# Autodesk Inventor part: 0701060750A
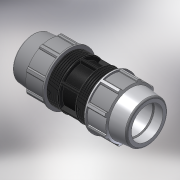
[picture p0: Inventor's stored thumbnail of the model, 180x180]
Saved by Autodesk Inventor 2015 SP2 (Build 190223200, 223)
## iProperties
Created: 2017-02
Part Number: 0701060750A
Material: Generic
Description: PLASSON COUPLER 75-75
Document SubType Name: Modeling
Designer: KIM
Mass: 3885.53 g
Surface Area: 4713.66 cm^2
Volume: 3885.53 cm^3
Density: 1 g/cm^3
Appearance: Default
Author: KIM
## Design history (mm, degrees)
derived "87010.ipt"
feature "Solid1::87010.ipt"
tag "TaggingFeature1"
body "Solid1"
other parameters: "d1" = 278, "d2" = 75, "d4" = 23.16667, "d5" = 39.71429, "d7" = 134, "d8" = 100.5, "d9" = 39.71429, "d11" = 3.97143, "d12" = 107.2, "d13" = 120 deg, "d14" = 105, "d15" = 6 deg, "d16" = 120.6, "d18" = 3.75, "d19" = 35 deg, "d20" = 17.5 deg, "d21" = 124.62, "d23" = 0, "d25" = 360 deg, "d27" = 2.68, "d33" = 1.5, "d34" = 6.7, "d36" = 0, "d37" = 1.5, "d38" = 1.5, "d40" = 360 deg, "d42" = 50.04, "d46" = 2.25, "d50" = 3.475, "d51" = 0, "d53" = 2.54171, "d54" = 2.54171, "d57" = 5.08343, "d62" = 118.188, "d64" = 67.5, "d65" = 138, "d_" = 75, "E_" = 134, "H_" = 278, "l_" = 138, "d52" = 25.41714
